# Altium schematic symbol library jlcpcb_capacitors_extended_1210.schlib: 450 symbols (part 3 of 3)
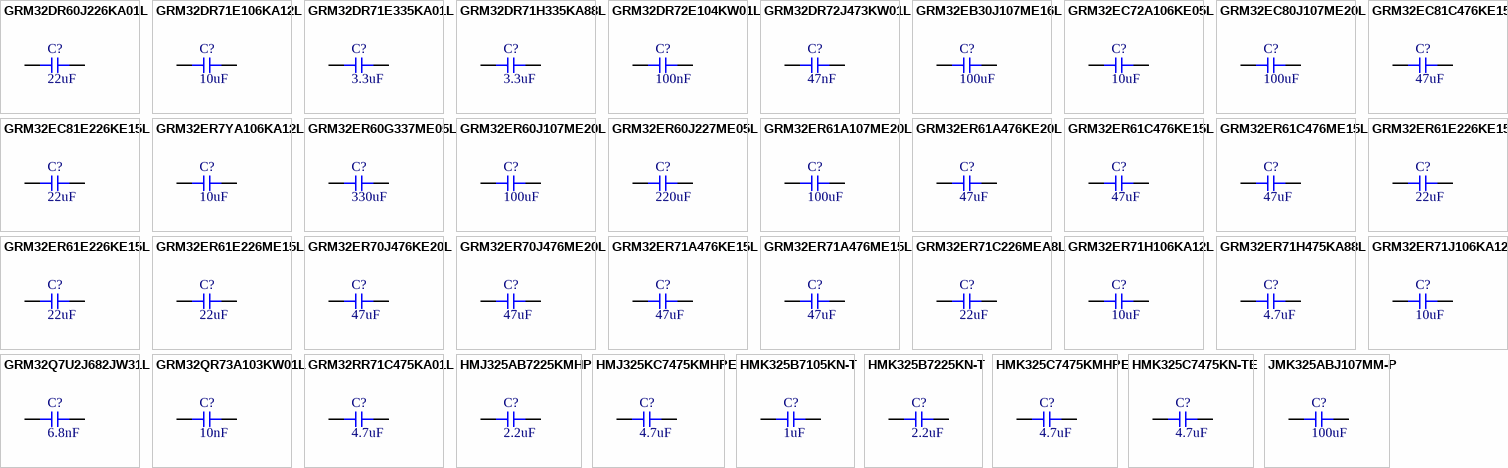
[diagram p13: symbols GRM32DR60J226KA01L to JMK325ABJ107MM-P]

## GRM32DR71H335KA88L
designator C?  Capacitance: 3.3uF  (hidden comment: *)
Capacitor, Ceramic (MLCC), 3.3uF, ±10%, 50V, X7R, ±10%, SMD 1210; Manufacturer: Murata Electronics; Manufacturer Part Number: GRM32DR71H335KA88L
footprint CAP-1210 (1210 (3225M) Capacitor)
pins: 1, 2

## GRM32DR72E104KW01L
designator C?  Capacitance: 100nF  (hidden comment: *)
Capacitor, Ceramic (MLCC), 100nF, ±10%, 250V, X7R, ±10%, SMD 1210; Manufacturer: Murata Electronics; Manufacturer Part Number: GRM32DR72E104KW01L
footprint CAP-1210 (1210 (3225M) Capacitor)
pins: 1, 2

## GRM32DR72J473KW01L
designator C?  Capacitance: 47nF  (hidden comment: *)
Capacitor, Ceramic (MLCC), 47nF, ±10%, 630V, X7R, ±10%, SMD 1210; Manufacturer: Murata Electronics; Manufacturer Part Number: GRM32DR72J473KW01L
footprint CAP-1210 (1210 (3225M) Capacitor)
pins: 1, 2

## GRM32EB30J107ME16L
designator C?  Capacitance: 100uF  (hidden comment: *)
Capacitor, Ceramic (MLCC), 100uF, ±20%, 6.3V, B, ±20%, SMD 1210; Manufacturer: Murata Electronics; Manufacturer Part Number: GRM32EB30J107ME16L
footprint CAP-1210 (1210 (3225M) Capacitor)
pins: 1, 2

## GRM32EC72A106KE05L
designator C?  Capacitance: 10uF  (hidden comment: *)
Capacitor, Ceramic (MLCC), 10uF, ±10%, ±10%, SMD 1210; Manufacturer: Murata Electronics; Manufacturer Part Number: GRM32EC72A106KE05L
footprint CAP-1210 (1210 (3225M) Capacitor)
pins: 1, 2

## GRM32EC80J107ME20L
designator C?  Capacitance: 100uF  (hidden comment: *)
Capacitor, Ceramic (MLCC), 100uF, ±20%, 6.3V, X6S, ±20%, SMD 1210; Manufacturer: Murata Electronics; Manufacturer Part Number: GRM32EC80J107ME20L
footprint CAP-1210 (1210 (3225M) Capacitor)
pins: 1, 2

## GRM32EC81C476KE15L
designator C?  Capacitance: 47uF  (hidden comment: *)
Capacitor, Ceramic (MLCC), 47uF, ±10%, 16V, X6S, ±10%, SMD 1210; Manufacturer: Murata Electronics; Manufacturer Part Number: GRM32EC81C476KE15L
footprint CAP-1210 (1210 (3225M) Capacitor)
pins: 1, 2

## GRM32EC81E226KE15L
designator C?  Capacitance: 22uF  (hidden comment: *)
Capacitor, Ceramic (MLCC), 22uF, ±10%, 25V, X6S, ±10%, SMD 1210; Manufacturer: Murata Electronics; Manufacturer Part Number: GRM32EC81E226KE15L
footprint CAP-1210 (1210 (3225M) Capacitor)
pins: 1, 2

## GRM32ER7YA106KA12L
designator C?  Capacitance: 10uF  (hidden comment: *)
Capacitor, Ceramic (MLCC), 10uF, ±10%, 35V, X7R, ±10%, SMD 1210; Manufacturer: Murata Electronics; Manufacturer Part Number: GRM32ER7YA106KA12L
footprint CAP-1210 (1210 (3225M) Capacitor)
pins: 1, 2

## GRM32ER60G337ME05L
designator C?  Capacitance: 330uF  (hidden comment: *)
Capacitor, Ceramic (MLCC), 330uF, ±20%, 4V, X5R, ±20%, SMD 1210; Manufacturer: Murata Electronics; Manufacturer Part Number: GRM32ER60G337ME05L
footprint CAP-1210 (1210 (3225M) Capacitor)
pins: 1, 2

## GRM32ER60J107ME20L
designator C?  Capacitance: 100uF  (hidden comment: *)
Capacitor, Ceramic (MLCC), 100uF, ±20%, 6.3V, X5R, ±20%, SMD 1210; Manufacturer: Murata Electronics; Manufacturer Part Number: GRM32ER60J107ME20L
footprint CAP-1210 (1210 (3225M) Capacitor)
pins: 1, 2

## GRM32ER60J227ME05L
designator C?  Capacitance: 220uF  (hidden comment: *)
Capacitor, Ceramic (MLCC), 220uF, ±20%, 6.3V, X5R, ±20%, SMD 1210; Manufacturer: Murata Electronics; Manufacturer Part Number: GRM32ER60J227ME05L
footprint CAP-1210 (1210 (3225M) Capacitor)
pins: 1, 2

## GRM32ER61A107ME20L
designator C?  Capacitance: 100uF  (hidden comment: *)
Capacitor, Ceramic (MLCC), 100uF, ±20%, 10V, X5R, ±20%, SMD 1210; Manufacturer: Murata Electronics; Manufacturer Part Number: GRM32ER61A107ME20L
footprint CAP-1210 (1210 (3225M) Capacitor)
pins: 1, 2

## GRM32ER61A476KE20L
designator C?  Capacitance: 47uF  (hidden comment: *)
Capacitor, Ceramic (MLCC), 47uF, ±10%, 10V, X5R, ±10%, SMD 1210; Manufacturer: Murata Electronics; Manufacturer Part Number: GRM32ER61A476KE20L
footprint CAP-1210 (1210 (3225M) Capacitor)
pins: 1, 2

## GRM32ER61C476KE15L
designator C?  Capacitance: 47uF  (hidden comment: *)
Capacitor, Ceramic (MLCC), 47uF, ±10%, 16V, X5R, ±10%, SMD 1210; Manufacturer: Murata Electronics; Manufacturer Part Number: GRM32ER61C476KE15L
footprint CAP-1210 (1210 (3225M) Capacitor)
pins: 1, 2

## GRM32ER61C476ME15L
designator C?  Capacitance: 47uF  (hidden comment: *)
Capacitor, Ceramic (MLCC), 47uF, ±20%, 16V, X5R, ±20%, SMD 1210; Manufacturer: Murata Electronics; Manufacturer Part Number: GRM32ER61C476ME15L
footprint CAP-1210 (1210 (3225M) Capacitor)
pins: 1, 2

## GRM32ER61E226KE15K
designator C?  Capacitance: 22uF  (hidden comment: *)
Capacitor, Ceramic (MLCC), 22uF, ±10%, 25V, X5R, ±10%, SMD 1210; Manufacturer: Murata Electronics; Manufacturer Part Number: GRM32ER61E226KE15K
footprint CAP-1210 (1210 (3225M) Capacitor)
pins: 1, 2

## GRM32ER61E226KE15L
designator C?  Capacitance: 22uF  (hidden comment: *)
Capacitor, Ceramic (MLCC), 22uF, ±10%, 25V, X5R, ±10%, SMD 1210; Manufacturer: Murata Electronics; Manufacturer Part Number: GRM32ER61E226KE15L
footprint CAP-1210 (1210 (3225M) Capacitor)
pins: 1, 2

## GRM32ER61E226ME15L
designator C?  Capacitance: 22uF  (hidden comment: *)
Capacitor, Ceramic (MLCC), 22uF, ±20%, 25V, X5R, ±20%, SMD 1210; Manufacturer: Murata Electronics; Manufacturer Part Number: GRM32ER61E226ME15L
footprint CAP-1210 (1210 (3225M) Capacitor)
pins: 1, 2

## GRM32ER70J476KE20L
designator C?  Capacitance: 47uF  (hidden comment: *)
Capacitor, Ceramic (MLCC), 47uF, ±10%, 6.3V, X7R, ±10%, SMD 1210; Manufacturer: Murata Electronics; Manufacturer Part Number: GRM32ER70J476KE20L
footprint CAP-1210 (1210 (3225M) Capacitor)
pins: 1, 2

## GRM32ER70J476ME20L
designator C?  Capacitance: 47uF  (hidden comment: *)
Capacitor, Ceramic (MLCC), 47uF, ±20%, 6.3V, X7R, ±20%, SMD 1210; Manufacturer: Murata Electronics; Manufacturer Part Number: GRM32ER70J476ME20L
footprint CAP-1210 (1210 (3225M) Capacitor)
pins: 1, 2

## GRM32ER71A476KE15L
designator C?  Capacitance: 47uF  (hidden comment: *)
Capacitor, Ceramic (MLCC), 47uF, ±10%, 10V, X7R, ±10%, SMD 1210; Manufacturer: Murata Electronics; Manufacturer Part Number: GRM32ER71A476KE15L
footprint CAP-1210 (1210 (3225M) Capacitor)
pins: 1, 2

## GRM32ER71A476ME15L
designator C?  Capacitance: 47uF  (hidden comment: *)
Capacitor, Ceramic (MLCC), 47uF, ±20%, 10V, X7R, ±20%, SMD 1210; Manufacturer: Murata Electronics; Manufacturer Part Number: GRM32ER71A476ME15L
footprint CAP-1210 (1210 (3225M) Capacitor)
pins: 1, 2

## GRM32ER71C226MEA8L
designator C?  Capacitance: 22uF  (hidden comment: *)
Capacitor, Ceramic (MLCC), 22uF, ±20%, 16V, X7R, ±20%, SMD 1210; Manufacturer: Murata Electronics; Manufacturer Part Number: GRM32ER71C226MEA8L
footprint CAP-1210 (1210 (3225M) Capacitor)
pins: 1, 2

## GRM32ER71H106KA12L
designator C?  Capacitance: 10uF  (hidden comment: *)
Capacitor, Ceramic (MLCC), 10uF, ±10%, 50V, X7R, ±10%, SMD 1210; Manufacturer: Murata Electronics; Manufacturer Part Number: GRM32ER71H106KA12L
footprint CAP-1210 (1210 (3225M) Capacitor)
pins: 1, 2

## GRM32ER71H475KA88L
designator C?  Capacitance: 4.7uF  (hidden comment: *)
Capacitor, Ceramic (MLCC), 4.7uF, ±10%, 50V, X7R, ±10%, SMD 1210; Manufacturer: Murata Electronics; Manufacturer Part Number: GRM32ER71H475KA88L
footprint CAP-1210 (1210 (3225M) Capacitor)
pins: 1, 2

## GRM32ER71J106KA12L
designator C?  Capacitance: 10uF  (hidden comment: *)
Capacitor, Ceramic (MLCC), 10uF, ±10%, ±10%, SMD 1210; Manufacturer: Murata Electronics; Manufacturer Part Number: GRM32ER71J106KA12L
footprint CAP-1210 (1210 (3225M) Capacitor)
pins: 1, 2

## GRM32Q7U2J682JW31L
designator C?  Capacitance: 6.8nF  (hidden comment: *)
Capacitor, Ceramic (MLCC), 6.8nF, ±5%, 630V, U2J, ±5%, SMD 1210; Manufacturer: Murata Electronics; Manufacturer Part Number: GRM32Q7U2J682JW31L
footprint CAP-1210 (1210 (3225M) Capacitor)
pins: 1, 2

## GRM32QR73A103KW01L
designator C?  Capacitance: 10nF  (hidden comment: *)
Capacitor, Ceramic (MLCC), 10nF, ±10%, 1kV, X7R, ±10%, SMD 1210; Manufacturer: Murata Electronics; Manufacturer Part Number: GRM32QR73A103KW01L
footprint CAP-1210 (1210 (3225M) Capacitor)
pins: 1, 2

## GRM32RR71C475KA01L
designator C?  Capacitance: 4.7uF  (hidden comment: *)
Capacitor, Ceramic (MLCC), 4.7uF, ±10%, ±10%, SMD 1210; Manufacturer: Murata Electronics; Manufacturer Part Number: GRM32RR71C475KA01L
footprint CAP-1210 (1210 (3225M) Capacitor)
pins: 1, 2

## HMJ325AB7225KMHP
designator C?  Capacitance: 2.2uF  (hidden comment: *)
Capacitor, Ceramic (MLCC), 2.2uF, ±10%, 100V, X7R, ±10%, SMD 1210; Manufacturer: Taiyo Yuden; Manufacturer Part Number: HMJ325AB7225KMHP
footprint CAP-1210 (1210 (3225M) Capacitor)
pins: 1, 2

## HMJ325KC7475KMHPE
designator C?  Capacitance: 4.7uF  (hidden comment: *)
Capacitor, Ceramic (MLCC), 4.7uF, ±10%, 100V, X7S, ±10%, SMD 1210; Manufacturer: Taiyo Yuden; Manufacturer Part Number: HMJ325KC7475KMHPE
footprint CAP-1210 (1210 (3225M) Capacitor)
pins: 1, 2

## HMK325B7105KN-T
designator C?  Capacitance: 1uF  (hidden comment: *)
Capacitor, Ceramic (MLCC), 1uF, ±10%, 100V, X7R, ±10%, SMD 1210; Manufacturer: Taiyo Yuden; Manufacturer Part Number: HMK325B7105KN-T
footprint CAP-1210 (1210 (3225M) Capacitor)
pins: 1, 2

## HMK325B7225KN-T
designator C?  Capacitance: 2.2uF  (hidden comment: *)
Capacitor, Ceramic (MLCC), 2.2uF, ±10%, 100V, X7R, ±10%, SMD 1210; Manufacturer: Taiyo Yuden; Manufacturer Part Number: HMK325B7225KN-T
footprint CAP-1210 (1210 (3225M) Capacitor)
pins: 1, 2

## HMK325C7475KMHPE
designator C?  Capacitance: 4.7uF  (hidden comment: *)
Capacitor, Ceramic (MLCC), 4.7uF, ±10%, 100V, X7S, ±10%, SMD 1210; Manufacturer: Taiyo Yuden; Manufacturer Part Number: HMK325C7475KMHPE
footprint CAP-1210 (1210 (3225M) Capacitor)
pins: 1, 2

## HMK325C7475KN-TE
designator C?  Capacitance: 4.7uF  (hidden comment: *)
Capacitor, Ceramic (MLCC), 4.7uF, ±10%, 100V, X7S, ±10%, SMD 1210; Manufacturer: Taiyo Yuden; Manufacturer Part Number: HMK325C7475KN-TE
footprint CAP-1210 (1210 (3225M) Capacitor)
pins: 1, 2

## JMK325ABJ107MM-P
designator C?  Capacitance: 100uF  (hidden comment: *)
Capacitor, Ceramic (MLCC), 100uF, ±20%, 6.3V, ±20%, SMD 1210; Manufacturer: Taiyo Yuden; Manufacturer Part Number: JMK325ABJ107MM-P
footprint CAP-1210 (1210 (3225M) Capacitor)
pins: 1, 2

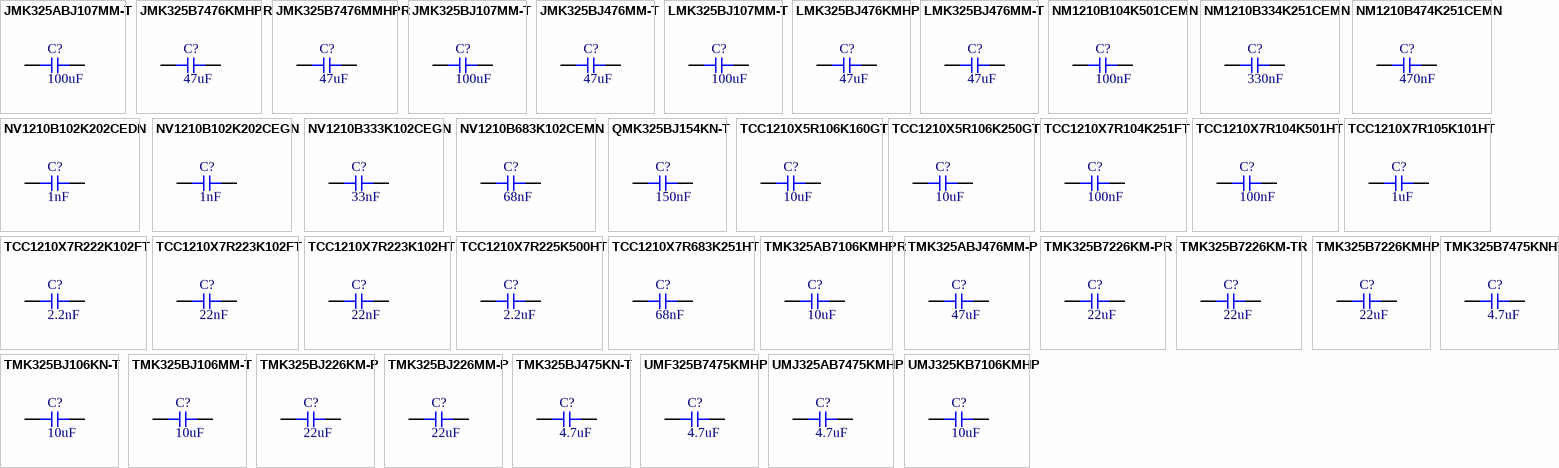
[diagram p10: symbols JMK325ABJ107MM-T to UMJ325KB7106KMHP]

## JMK325ABJ107MM-T
designator C?  Capacitance: 100uF  (hidden comment: *)
Capacitor, Ceramic (MLCC), 100uF, ±20%, 6.3V, X5R, ±20%, SMD 1210; Manufacturer: Taiyo Yuden; Manufacturer Part Number: JMK325ABJ107MM-T
footprint CAP-1210 (1210 (3225M) Capacitor)
pins: 1, 2

## JMK325B7476KMHPR
designator C?  Capacitance: 47uF  (hidden comment: *)
Capacitor, Ceramic (MLCC), 47uF, ±10%, 6.3V, X7R, ±10%, SMD 1210; Manufacturer: Taiyo Yuden; Manufacturer Part Number: JMK325B7476KMHPR
footprint CAP-1210 (1210 (3225M) Capacitor)
pins: 1, 2

## JMK325B7476MMHPR
designator C?  Capacitance: 47uF  (hidden comment: *)
Capacitor, Ceramic (MLCC), 47uF, ±20%, 6.3V, X7R, ±20%, SMD 1210; Manufacturer: Taiyo Yuden; Manufacturer Part Number: JMK325B7476MMHPR
footprint CAP-1210 (1210 (3225M) Capacitor)
pins: 1, 2

## JMK325BJ107MM-T
designator C?  Capacitance: 100uF  (hidden comment: *)
Capacitor, Ceramic (MLCC), 100uF, ±20%, 6.3V, X5R, ±20%, SMD 1210; Manufacturer: Taiyo Yuden; Manufacturer Part Number: JMK325BJ107MM-T
footprint CAP-1210 (1210 (3225M) Capacitor)
pins: 1, 2

## JMK325BJ476MM-T
designator C?  Capacitance: 47uF  (hidden comment: *)
Capacitor, Ceramic (MLCC), 47uF, ±20%, 6.3V, X5R, ±20%, SMD 1210; Manufacturer: Taiyo Yuden; Manufacturer Part Number: JMK325BJ476MM-T
footprint CAP-1210 (1210 (3225M) Capacitor)
pins: 1, 2

## LMK325BJ107MM-T
designator C?  Capacitance: 100uF  (hidden comment: *)
Capacitor, Ceramic (MLCC), 100uF, ±20%, 10V, X5R, ±20%, SMD 1210; Manufacturer: Taiyo Yuden; Manufacturer Part Number: LMK325BJ107MM-T
footprint CAP-1210 (1210 (3225M) Capacitor)
pins: 1, 2

## LMK325BJ476KMHP
designator C?  Capacitance: 47uF  (hidden comment: *)
Capacitor, Ceramic (MLCC), 47uF, ±10%, 10V, X5R, ±10%, SMD 1210; Manufacturer: Taiyo Yuden; Manufacturer Part Number: LMK325BJ476KMHP
footprint CAP-1210 (1210 (3225M) Capacitor)
pins: 1, 2

## LMK325BJ476MM-T
designator C?  Capacitance: 47uF  (hidden comment: *)
Capacitor, Ceramic (MLCC), 47uF, ±20%, 10V, X5R, ±20%, SMD 1210; Manufacturer: Taiyo Yuden; Manufacturer Part Number: LMK325BJ476MM-T
footprint CAP-1210 (1210 (3225M) Capacitor)
pins: 1, 2

## NM1210B104K501CEMN
designator C?  Capacitance: 100nF  (hidden comment: *)
Capacitor, Ceramic (MLCC), 100nF, ±10%, 500V, X7R, ±10%, SMD 1210; Manufacturer: HUI JU; Manufacturer Part Number: NM1210B104K501CEMN
footprint CAP-1210 (1210 (3225M) Capacitor)
pins: 1, 2

## NM1210B334K251CEMN
designator C?  Capacitance: 330nF  (hidden comment: *)
Capacitor, Ceramic (MLCC), 330nF, ±10%, 250V, X7R, ±10%, SMD 1210; Manufacturer: HUI JU; Manufacturer Part Number: NM1210B334K251CEMN
footprint CAP-1210 (1210 (3225M) Capacitor)
pins: 1, 2

## NM1210B474K251CEMN
designator C?  Capacitance: 470nF  (hidden comment: *)
Capacitor, Ceramic (MLCC), 470nF, ±10%, 250V, X7R, ±10%, SMD 1210; Manufacturer: HUI JU; Manufacturer Part Number: NM1210B474K251CEMN
footprint CAP-1210 (1210 (3225M) Capacitor)
pins: 1, 2

## NV1210B102K202CEDN
designator C?  Capacitance: 1nF  (hidden comment: *)
Capacitor, Ceramic (MLCC), 1nF, ±10%, 2kV, ±10%, SMD 1210; Manufacturer: HUI JU; Manufacturer Part Number: NV1210B102K202CEDN
footprint CAP-1210 (1210 (3225M) Capacitor)
pins: 1, 2

## NV1210B102K202CEGN
designator C?  Capacitance: 1nF  (hidden comment: *)
Capacitor, Ceramic (MLCC), 1nF, ±10%, 2kV, ±10%, SMD 1210; Manufacturer: HUI JU; Manufacturer Part Number: NV1210B102K202CEGN
footprint CAP-1210 (1210 (3225M) Capacitor)
pins: 1, 2

## NV1210B333K102CEGN
designator C?  Capacitance: 33nF  (hidden comment: *)
Capacitor, Ceramic (MLCC), 33nF, ±10%, 1kV, X7R, ±10%, SMD 1210; Manufacturer: HUI JU; Manufacturer Part Number: NV1210B333K102CEGN
footprint CAP-1210 (1210 (3225M) Capacitor)
pins: 1, 2

## NV1210B683K102CEMN
designator C?  Capacitance: 68nF  (hidden comment: *)
Capacitor, Ceramic (MLCC), 68nF, ±10%, 1kV, X7R, ±10%, SMD 1210; Manufacturer: HUI JU; Manufacturer Part Number: NV1210B683K102CEMN
footprint CAP-1210 (1210 (3225M) Capacitor)
pins: 1, 2

## QMK325BJ154KN-T
designator C?  Capacitance: 150nF  (hidden comment: *)
Capacitor, Ceramic (MLCC), 150nF, ±10%, 250V, X5R, ±10%, SMD 1210; Manufacturer: Taiyo Yuden; Manufacturer Part Number: QMK325BJ154KN-T
footprint CAP-1210 (1210 (3225M) Capacitor)
pins: 1, 2

## TCC1210X5R106K160GT
designator C?  Capacitance: 10uF  (hidden comment: *)
Capacitor, Ceramic (MLCC), 10uF, ±10%, 16V, X5R, ±10%, SMD 1210; Manufacturer: CCTC; Manufacturer Part Number: TCC1210X5R106K160GT
footprint CAP-1210 (1210 (3225M) Capacitor)
pins: 1, 2

## TCC1210X5R106K250GT
designator C?  Capacitance: 10uF  (hidden comment: *)
Capacitor, Ceramic (MLCC), 10uF, ±10%, 25V, X5R, ±10%, SMD 1210; Manufacturer: CCTC; Manufacturer Part Number: TCC1210X5R106K250GT
footprint CAP-1210 (1210 (3225M) Capacitor)
pins: 1, 2

## TCC1210X7R104K251FT
designator C?  Capacitance: 100nF  (hidden comment: *)
Capacitor, Ceramic (MLCC), 100nF, ±10%, 250V, X7R, ±10%, SMD 1210; Manufacturer: CCTC; Manufacturer Part Number: TCC1210X7R104K251FT
footprint CAP-1210 (1210 (3225M) Capacitor)
pins: 1, 2

## TCC1210X7R104K501HT
designator C?  Capacitance: 100nF  (hidden comment: *)
Capacitor, Ceramic (MLCC), 100nF, ±10%, 500V, X7R, ±10%, SMD 1210; Manufacturer: CCTC; Manufacturer Part Number: TCC1210X7R104K501HT
footprint CAP-1210 (1210 (3225M) Capacitor)
pins: 1, 2

## TCC1210X7R105K101HT
designator C?  Capacitance: 1uF  (hidden comment: *)
Capacitor, Ceramic (MLCC), 1uF, ±10%, 100V, X7R, ±10%, SMD 1210; Manufacturer: CCTC; Manufacturer Part Number: TCC1210X7R105K101HT
footprint CAP-1210 (1210 (3225M) Capacitor)
pins: 1, 2

## TCC1210X7R222K102FT
designator C?  Capacitance: 2.2nF  (hidden comment: *)
Capacitor, Ceramic (MLCC), 2.2nF, ±10%, 1kV, X7R, ±10%, SMD 1210; Manufacturer: CCTC; Manufacturer Part Number: TCC1210X7R222K102FT
footprint CAP-1210 (1210 (3225M) Capacitor)
pins: 1, 2

## TCC1210X7R223K102FT
designator C?  Capacitance: 22nF  (hidden comment: *)
Capacitor, Ceramic (MLCC), 22nF, ±10%, 1kV, X7R, ±10%, SMD 1210; Manufacturer: CCTC; Manufacturer Part Number: TCC1210X7R223K102FT
footprint CAP-1210 (1210 (3225M) Capacitor)
pins: 1, 2

## TCC1210X7R223K102HT
designator C?  Capacitance: 22nF  (hidden comment: *)
Capacitor, Ceramic (MLCC), 22nF, ±10%, 1kV, X7R, ±10%, SMD 1210; Manufacturer: CCTC; Manufacturer Part Number: TCC1210X7R223K102HT
footprint CAP-1210 (1210 (3225M) Capacitor)
pins: 1, 2

## TCC1210X7R225K500HT
designator C?  Capacitance: 2.2uF  (hidden comment: *)
Capacitor, Ceramic (MLCC), 2.2uF, ±10%, 50V, X7R, ±10%, SMD 1210; Manufacturer: CCTC; Manufacturer Part Number: TCC1210X7R225K500HT
footprint CAP-1210 (1210 (3225M) Capacitor)
pins: 1, 2

## TCC1210X7R683K251HT
designator C?  Capacitance: 68nF  (hidden comment: *)
Capacitor, Ceramic (MLCC), 68nF, ±10%, 250V, X7R, ±10%, SMD 1210; Manufacturer: CCTC; Manufacturer Part Number: TCC1210X7R683K251HT
footprint CAP-1210 (1210 (3225M) Capacitor)
pins: 1, 2

## TMK325AB7106KMHPR
designator C?  Capacitance: 10uF  (hidden comment: *)
Capacitor, Ceramic (MLCC), 10uF, ±10%, 25V, X7R, ±10%, SMD 1210; Manufacturer: Taiyo Yuden; Manufacturer Part Number: TMK325AB7106KMHPR
footprint CAP-1210 (1210 (3225M) Capacitor)
pins: 1, 2

## TMK325ABJ476MM-P
designator C?  Capacitance: 47uF  (hidden comment: *)
Capacitor, Ceramic (MLCC), 47uF, ±20%, 25V, X5R, ±20%, SMD 1210; Manufacturer: Taiyo Yuden; Manufacturer Part Number: TMK325ABJ476MM-P
footprint CAP-1210 (1210 (3225M) Capacitor)
pins: 1, 2

## TMK325B7226KM-PR
designator C?  Capacitance: 22uF  (hidden comment: *)
Capacitor, Ceramic (MLCC), 22uF, ±10%, 25V, X7R, ±10%, SMD 1210; Manufacturer: Taiyo Yuden; Manufacturer Part Number: TMK325B7226KM-PR
footprint CAP-1210 (1210 (3225M) Capacitor)
pins: 1, 2

## TMK325B7226KM-TR
designator C?  Capacitance: 22uF  (hidden comment: *)
Capacitor, Ceramic (MLCC), 22uF, ±10%, 25V, X7R, ±10%, SMD 1210; Manufacturer: Taiyo Yuden; Manufacturer Part Number: TMK325B7226KM-TR
footprint CAP-1210 (1210 (3225M) Capacitor)
pins: 1, 2

## TMK325B7226KMHP
designator C?  Capacitance: 22uF  (hidden comment: *)
Capacitor, Ceramic (MLCC), 22uF, ±10%, 25V, X7R, ±10%, SMD 1210; Manufacturer: Taiyo Yuden; Manufacturer Part Number: TMK325B7226KMHP
footprint CAP-1210 (1210 (3225M) Capacitor)
pins: 1, 2

## TMK325B7475KNHT
designator C?  Capacitance: 4.7uF  (hidden comment: *)
Capacitor, Ceramic (MLCC), 4.7uF, ±10%, 25V, X7R, ±10%, SMD 1210; Manufacturer: Taiyo Yuden; Manufacturer Part Number: TMK325B7475KNHT
footprint CAP-1210 (1210 (3225M) Capacitor)
pins: 1, 2

## TMK325BJ106KN-T
designator C?  Capacitance: 10uF  (hidden comment: *)
Capacitor, Ceramic (MLCC), 10uF, ±10%, 25V, X5R, ±10%, SMD 1210; Manufacturer: Taiyo Yuden; Manufacturer Part Number: TMK325BJ106KN-T
footprint CAP-1210 (1210 (3225M) Capacitor)
pins: 1, 2

## TMK325BJ106MM-T
designator C?  Capacitance: 10uF  (hidden comment: *)
Capacitor, Ceramic (MLCC), 10uF, ±20%, 25V, X5R, ±20%, SMD 1210; Manufacturer: Taiyo Yuden; Manufacturer Part Number: TMK325BJ106MM-T
footprint CAP-1210 (1210 (3225M) Capacitor)
pins: 1, 2

## TMK325BJ226KM-P
designator C?  Capacitance: 22uF  (hidden comment: *)
Capacitor, Ceramic (MLCC), 22uF, ±10%, 25V, X5R, ±10%, SMD 1210; Manufacturer: Taiyo Yuden; Manufacturer Part Number: TMK325BJ226KM-P
footprint CAP-1210 (1210 (3225M) Capacitor)
pins: 1, 2

## TMK325BJ226MM-P
designator C?  Capacitance: 22uF  (hidden comment: *)
Capacitor, Ceramic (MLCC), 22uF, ±20%, 25V, X5R, ±20%, SMD 1210; Manufacturer: Taiyo Yuden; Manufacturer Part Number: TMK325BJ226MM-P
footprint CAP-1210 (1210 (3225M) Capacitor)
pins: 1, 2

## TMK325BJ475KN-T
designator C?  Capacitance: 4.7uF  (hidden comment: *)
Capacitor, Ceramic (MLCC), 4.7uF, ±10%, 25V, X5R, ±10%, SMD 1210; Manufacturer: Taiyo Yuden; Manufacturer Part Number: TMK325BJ475KN-T
footprint CAP-1210 (1210 (3225M) Capacitor)
pins: 1, 2

## UMF325B7475KMHP
designator C?  Capacitance: 4.7uF  (hidden comment: *)
Capacitor, Ceramic (MLCC), 4.7uF, ±10%, 50V, X7R, ±10%, SMD 1210; Manufacturer: Taiyo Yuden; Manufacturer Part Number: UMF325B7475KMHP
footprint CAP-1210 (1210 (3225M) Capacitor)
pins: 1, 2

## UMJ325AB7475KMHP
designator C?  Capacitance: 4.7uF  (hidden comment: *)
Capacitor, Ceramic (MLCC), 4.7uF, ±10%, 50V, X7R, ±10%, SMD 1210; Manufacturer: Taiyo Yuden; Manufacturer Part Number: UMJ325AB7475KMHP
footprint CAP-1210 (1210 (3225M) Capacitor)
pins: 1, 2

## UMJ325KB7106KMHP
designator C?  Capacitance: 10uF  (hidden comment: *)
Capacitor, Ceramic (MLCC), 10uF, ±10%, 50V, X7R, ±10%, SMD 1210; Manufacturer: Taiyo Yuden; Manufacturer Part Number: UMJ325KB7106KMHP
footprint CAP-1210 (1210 (3225M) Capacitor)
pins: 1, 2

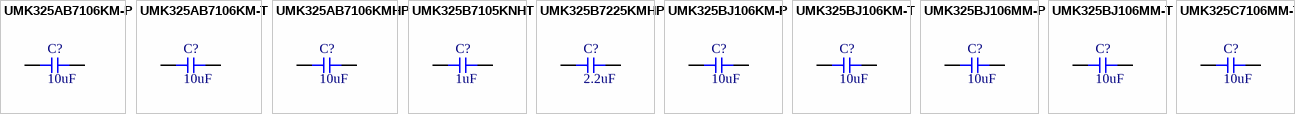
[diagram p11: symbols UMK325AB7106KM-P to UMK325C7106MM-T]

## UMK325AB7106KM-P
designator C?  Capacitance: 10uF  (hidden comment: *)
Capacitor, Ceramic (MLCC), 10uF, ±10%, 50V, X7R, ±10%, SMD 1210; Manufacturer: Taiyo Yuden; Manufacturer Part Number: UMK325AB7106KM-P
footprint CAP-1210 (1210 (3225M) Capacitor)
pins: 1, 2

## UMK325AB7106KM-T
designator C?  Capacitance: 10uF  (hidden comment: *)
Capacitor, Ceramic (MLCC), 10uF, ±10%, 50V, X7R, ±10%, SMD 1210; Manufacturer: Taiyo Yuden; Manufacturer Part Number: UMK325AB7106KM-T
footprint CAP-1210 (1210 (3225M) Capacitor)
pins: 1, 2

## UMK325AB7106KMHP
designator C?  Capacitance: 10uF  (hidden comment: *)
Capacitor, Ceramic (MLCC), 10uF, ±10%, 50V, X7R, ±10%, SMD 1210; Manufacturer: Taiyo Yuden; Manufacturer Part Number: UMK325AB7106KMHP
footprint CAP-1210 (1210 (3225M) Capacitor)
pins: 1, 2

## UMK325B7105KNHT
designator C?  Capacitance: 1uF  (hidden comment: *)
Capacitor, Ceramic (MLCC), 1uF, ±10%, 50V, X7R, ±10%, SMD 1210; Manufacturer: Taiyo Yuden; Manufacturer Part Number: UMK325B7105KNHT
footprint CAP-1210 (1210 (3225M) Capacitor)
pins: 1, 2

## UMK325B7225KMHP
designator C?  Capacitance: 2.2uF  (hidden comment: *)
Capacitor, Ceramic (MLCC), 2.2uF, ±10%, 50V, X7R, ±10%, SMD 1210; Manufacturer: Taiyo Yuden; Manufacturer Part Number: UMK325B7225KMHP
footprint CAP-1210 (1210 (3225M) Capacitor)
pins: 1, 2

## UMK325BJ106KM-P
designator C?  Capacitance: 10uF  (hidden comment: *)
Capacitor, Ceramic (MLCC), 10uF, ±10%, 50V, ±10%, SMD 1210; Manufacturer: Taiyo Yuden; Manufacturer Part Number: UMK325BJ106KM-P
footprint CAP-1210 (1210 (3225M) Capacitor)
pins: 1, 2

## UMK325BJ106KM-T
designator C?  Capacitance: 10uF  (hidden comment: *)
Capacitor, Ceramic (MLCC), 10uF, ±10%, 50V, X5R, ±10%, SMD 1210; Manufacturer: Taiyo Yuden; Manufacturer Part Number: UMK325BJ106KM-T
footprint CAP-1210 (1210 (3225M) Capacitor)
pins: 1, 2

## UMK325BJ106MM-P
designator C?  Capacitance: 10uF  (hidden comment: *)
Capacitor, Ceramic (MLCC), 10uF, ±20%, 50V, X5R, ±20%, SMD 1210; Manufacturer: Taiyo Yuden; Manufacturer Part Number: UMK325BJ106MM-P
footprint CAP-1210 (1210 (3225M) Capacitor)
pins: 1, 2

## UMK325BJ106MM-T
designator C?  Capacitance: 10uF  (hidden comment: *)
Capacitor, Ceramic (MLCC), 10uF, ±20%, 50V, X5R, ±20%, SMD 1210; Manufacturer: Taiyo Yuden; Manufacturer Part Number: UMK325BJ106MM-T
footprint CAP-1210 (1210 (3225M) Capacitor)
pins: 1, 2

## UMK325C7106MM-T
designator C?  Capacitance: 10uF  (hidden comment: *)
Capacitor, Ceramic (MLCC), 10uF, ±20%, 50V, X7S, ±20%, SMD 1210; Manufacturer: Taiyo Yuden; Manufacturer Part Number: UMK325C7106MM-T
footprint CAP-1210 (1210 (3225M) Capacitor)
pins: 1, 2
